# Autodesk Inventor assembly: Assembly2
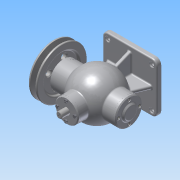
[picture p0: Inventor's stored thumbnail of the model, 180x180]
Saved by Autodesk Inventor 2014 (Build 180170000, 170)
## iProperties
Created: 2017-01
Part Number: Assembly2
Document SubType Name: Assembly
Designer: ksu
Author: ksu
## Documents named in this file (19)
- C:\Users\ksu\Desktop\470118V1015 (2)\Assembly2.iam
- C:\Users\ksu\Desktop\470118V1015 (2)\1본체.ipt
- C:\Users\ksu\Desktop\470118V1015 (2)\V-벨트풀리.ipt
- C:\Users\ksu\Desktop\470118V1015 (2)\너트 M8.ipt
- C:\Users\ksu\Desktop\470118V1015 (2)\뒤커버.ipt
- C:\Users\ksu\Desktop\470118V1015 (2)\멈춤링- 15 x 1.ipt
- C:\Users\ksu\Desktop\470118V1015 (2)\멈춤링- 35x1.6.ipt
- KS B 1336 - 35x1.6.ipt
- C:\Users\ksu\Desktop\470118V1015 (2)\베어링- 6202.ipt
- KS B 2023 - 6202 - 15 x 35 x 11 - 7.8.ipt
- C:\Users\ksu\Desktop\470118V1015 (2)\볼트 M4 x 12.ipt
- C:\Users\ksu\Desktop\470118V1015 (2)\볼트 M4 x 16.ipt
- C:\Users\ksu\Desktop\470118V1015 (2)\부시.ipt
- C:\Users\ksu\Desktop\470118V1015 (2)\상부커버.ipt
- C:\Users\ksu\Desktop\470118V1015 (2)\슬라이드.ipt
- C:\Users\ksu\Desktop\470118V1015 (2)\앞커버.ipt
- C:\Users\ksu\Desktop\470118V1015 (2)\오일실 15 30 7.ipt
- C:\Users\ksu\Desktop\470118V1015 (2)\키 4 x 4 x 12.ipt
- C:\Users\ksu\Desktop\470118V1015 (2)\편심축.ipt
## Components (17 placed, 6 different names)
1. 1본체:1 — Mate:1, Insert:1, Mate:2, Insert:2, Mate:3, Insert:3, Mate:12, Mate:13, Mate:14, Mate:16, Mate:18
2. V-벨트풀리:1 — Mate:9, Insert:6, Mate:11
3. KS B 1336 - 35x1.6:1 — Mate:12, Mate:13, Mate:15
4. KS B 2023 - 6202 - 15 x 35 x 11 - 7.8:1 — Insert:5, Mate:20
5. KS B 2023 - 6202 - 15 x 35 x 11 - 7.8:2 — Mate:14, Mate:15, Mate:17
6. ISO 4762 M4 x 16:1 — Insert:7
7. ISO 4762 M4 x 16:2
8. ISO 4762 M4 x 16:3
9. ISO 4762 M4 x 16:4
10. ISO 4762 M4 x 16:5 — Mate:22, Mate:23
11. ISO 4762 M4 x 16:6
12. ISO 4762 M4 x 16:7
13. ISO 4762 M4 x 16:8
14. KS B 1021 - 에 따름 ISO 1207 - 미터 A  M 4 x 12:1 — Mate:24, Mate:25
15. KS B 1021 - 에 따름 ISO 1207 - 미터 A  M 4 x 12:2
16. KS B 1021 - 에 따름 ISO 1207 - 미터 A  M 4 x 12:3
17. KS B 1021 - 에 따름 ISO 1207 - 미터 A  M 4 x 12:4
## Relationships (23: Mate 17, Insert 6)
- Mate:1: 1본체:1
- Insert:1: 1본체:1
- Mate:2: 1본체:1
- Insert:2: 1본체:1
- Mate:3: 1본체:1
- Insert:3: 1본체:1
- Insert:5: KS B 2023 - 6202 - 15 x 35 x 11 - 7.8:1
- Mate:9: V-벨트풀리:1
- Insert:6: V-벨트풀리:1
- Mate:11: V-벨트풀리:1
- Mate:12: 1본체:1 ↔ KS B 1336 - 35x1.6:1
- Mate:13: 1본체:1 ↔ KS B 1336 - 35x1.6:1
- Mate:14: 1본체:1 ↔ KS B 2023 - 6202 - 15 x 35 x 11 - 7.8:2
- Mate:15: KS B 1336 - 35x1.6:1 ↔ KS B 2023 - 6202 - 15 x 35 x 11 - 7.8:2
- Mate:16: 1본체:1
- Mate:17: KS B 2023 - 6202 - 15 x 35 x 11 - 7.8:2
- Mate:18: 1본체:1
- Mate:20: KS B 2023 - 6202 - 15 x 35 x 11 - 7.8:1
- Insert:7: ISO 4762 M4 x 16:1
- Mate:22: ISO 4762 M4 x 16:5
- Mate:23: ISO 4762 M4 x 16:5
- Mate:24: KS B 1021 - 에 따름 ISO 1207 - 미터 A  M 4 x 12:1
- Mate:25: KS B 1021 - 에 따름 ISO 1207 - 미터 A  M 4 x 12:1
